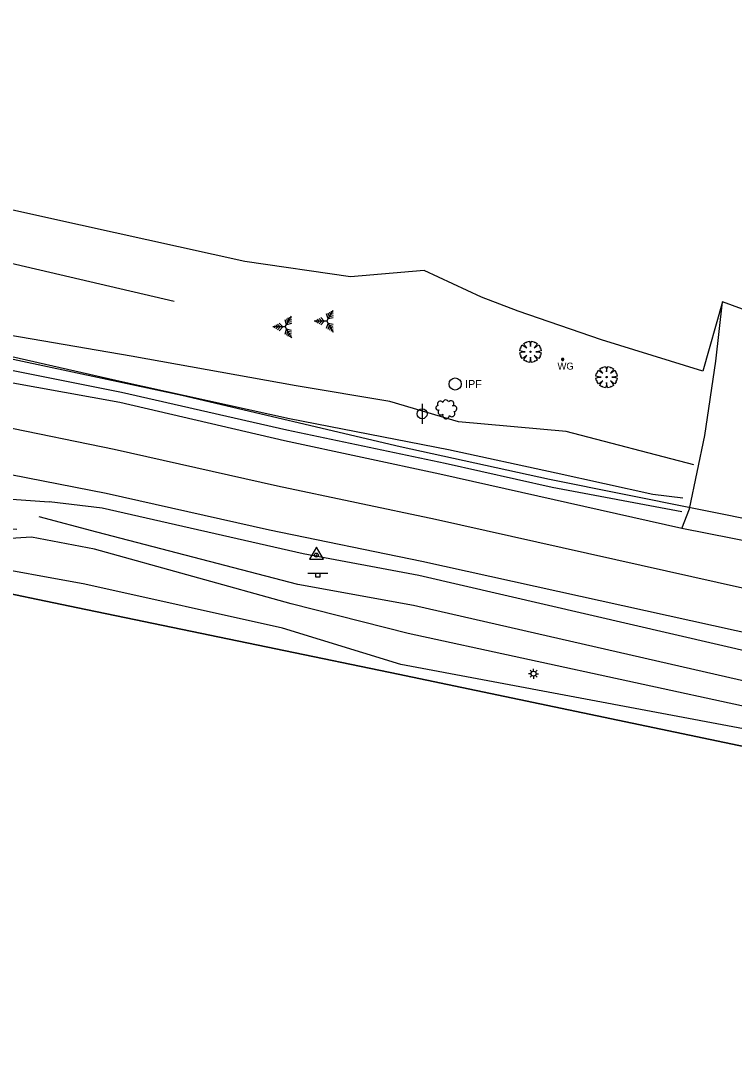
# Model space of a CAD drawing. Extents: x 1158469 to 1165378, y 609843 to 611748.
# Drawn here: x 1164593 to 1164771.4, y 610055.1 to 610312.5 of the extents above; entities that cross this region are included whole.
import ezdxf

# ---------------------------------------------------------------- set-up
doc = ezdxf.new("R2010")
doc.units = 0
for name, color, linetype in [('Exterior Boundary', 7, 'Continuous'), ('S_Control_Temp_Traverse', 7, 'Continuous'), ('S_Fencing_ChainLink', 7, 'Continuous'), ('S_Ground_Elevation', 7, 'Continuous'), ('S_Property_IronPipeFound', 7, 'Continuous'), ('S_Property_Light', 7, 'Continuous'), ('S_Property_Well_GroundElevation', 7, 'Continuous'), ('S_Roadway_Centerline', 7, 'Continuous'), ('S_Roadway_Drive_Gravel', 7, 'Continuous'), ('S_Roadway_Drive_Paved', 7, 'Continuous'), ('S_Roadway_Edge_Pavement', 7, 'Continuous'), ('S_Traffic_Sign_SinglePost', 7, 'Continuous'), ('S_Trees_Bush', 7, 'Continuous'), ('S_Trees_Conifer_NonPay', 7, 'Continuous'), ('S_Trees_Decid_NonPay', 7, 'Continuous'), ('S_Trees_HedgeLine', 7, 'Continuous'), ('S_Utilities_Pole_Power', 7, 'Continuous'), ('S_Utilities_UG_Gas_Line', 7, 'Continuous')]:
    doc.layers.add(name, color=color, linetype=linetype)

msp = doc.modelspace()

# ---------------------------------------------------------------- linework, layer by layer
at = {"layer": 'Exterior Boundary'}
for points in [[(1164903.83, 610193.7), (1164863.2, 610204), (1164861.53, 610205.25), (1164858.1, 610207.6), (1164854.54, 610209.76), (1164852.11, 610211.1), (1164847.14, 610213.54), (1164843.1, 610215.24), (1164841.05, 610216.01), (1164837.94, 610217.07), (1164833.18, 610218.44), (1164768.45, 610242.22), (1164763.58, 610224.84), (1164738.2, 610232.74), (1164717.42, 610239.88), (1164708.24, 610243.35), (1164693.9, 610250.06), (1164675.49, 610248.43), (1164649.1, 610252.28), (1164600.08, 610263.12), (1164566.81, 610270.51)], [(1164407.45, 610200.7), (1164438.65, 610196.65), (1164457.36, 610193.85), (1164478.6, 610190.25), (1164498.72, 610183.81), (1164514.58, 610168.55), (1164581.36, 610170.69), (1164581.72, 610171.1), (1164607.36, 610165.71), (1164656.83, 610155.47), (1164687.39, 610149.15), (1164772.52, 610131.34), (1164815.65, 610122.37), (1164871.7, 610110.37), (1164887.39, 610105.37), (1164928.57, 610096.9)]]:
    msp.add_lwpolyline(points, dxfattribs=at)
at = {"layer": 'S_Control_Temp_Traverse'}
for p, q in [((1164666.85, 610178.9), (1164667.1, 610178.9)), ((1164666.97, 610179.03), (1164666.97, 610178.78))]:
    msp.add_line(p, q, dxfattribs=at)
msp.add_lwpolyline([(1164665.24, 610177.9), (1164668.71, 610177.9), (1164666.97, 610180.9)], close=True, dxfattribs=at)
msp.add_circle((1164666.97, 610178.9), 0.5, dxfattribs=at)
at = {"layer": 'S_Fencing_ChainLink'}
msp.add_lwpolyline([(1164869.51, 610100.35), (1164871.7, 610110.37), (1164815.65, 610122.37), (1164772.52, 610131.34), (1164687.39, 610149.15), (1164656.83, 610155.47), (1164607.36, 610165.71), (1164581.72, 610171.1), (1164574.63, 610139.83), (1164560.56, 610143.01)], dxfattribs=at)
at = {"layer": 'S_Ground_Elevation'}
for points in [[(1164763.58, 610224.84), (1164738.2, 610232.74), (1164717.42, 610239.88), (1164708.24, 610243.35), (1164693.9, 610250.06), (1164675.49, 610248.43), (1164649.1, 610252.28), (1164600.08, 610263.12), (1164566.81, 610270.51), (1164538.66, 610273.93), (1164498.09, 610279.94), (1164480.73, 610283.61), (1164457.41, 610282.8), (1164453.66, 610297.23), (1164453.93, 610312.49)], [(1164761.29, 610201.44), (1164729.39, 610209.78), (1164702.48, 610212.22), (1164685.33, 610217.31), (1164661.9, 610221.24), (1164620.7, 610228.6), (1164590.08, 610233.86), (1164556.37, 610241.22), (1164527.86, 610249.08), (1164496.26, 610253.68), (1164468.26, 610259.85), (1164455.55, 610263.46)], [(1164758.29, 610189.71), (1164725.91, 610195.8), (1164699.15, 610201.83), (1164659.56, 610210.14), (1164618.3, 610219.54), (1164588.26, 610225.54), (1164554.8, 610231.9), (1164525.78, 610237.71), (1164494.09, 610244.67), (1164467.1, 610249.14), (1164452.39, 610252.67), (1164442.78, 610255.45), (1164439.6, 610257.87), (1164438.33, 610260.82)], [(1164758.56, 610193.13), (1164751.06, 610194.06), (1164726.93, 610199.41), (1164699.99, 610205.18), (1164660.26, 610212.97), (1164618.7, 610222.1), (1164589.01, 610228.9), (1164555.36, 610235.61), (1164526.59, 610241.94), (1164495.09, 610248.39), (1164467.66, 610253.8), (1164454.39, 610257.4), (1164441.36, 610259.91)], [(1164937.87, 610100.73), (1164888.97, 610111.32), (1164813.69, 610124.81), (1164773.68, 610135.52), (1164688.09, 610151.59), (1164658.53, 610160.64), (1164609.13, 610171.64), (1164581.57, 610176.61), (1164575.27, 610182.72), (1164576.93, 610186.53), (1164581.1, 610189.86), (1164590.89, 610192.87), (1164600.18, 610192.25)], [(1164949.24, 610096.19), (1164972.18, 610091.41), (1165006.8, 610084.96), (1165049.11, 610075.28), (1165077.78, 610072.21), (1165082.39, 610077.32), (1165083.55, 610085.15), (1165057.81, 610094.68), (1165021.71, 610103.76), (1164992.93, 610110.39), (1164953.46, 610118.26), (1164916.46, 610126.06), (1164891.26, 610129.22), (1164870.42, 610136.28), (1164819.53, 610147.22), (1164777.52, 610154.18), (1164692.53, 610173.85), (1164663.65, 610179.23), (1164613.39, 610190.6), (1164600.18, 610192.25)], [(1164949.51, 610110.94), (1164891.13, 610123.39), (1164817.42, 610139.44), (1164776.14, 610146.9), (1164691.23, 610166.29), (1164662.34, 610171.55), (1164612.06, 610184.67), (1164597.68, 610188.51)], [(1164946.72, 610105.38), (1164890.19, 610118.57), (1164815.41, 610133.93), (1164775.15, 610140.78), (1164689.92, 610159.35), (1164660.69, 610166.76), (1164611.52, 610180.36), (1164595.78, 610183.41), (1164582.5, 610182.59), (1164578.91, 610185.44), (1164583.71, 610185.64), (1164592.14, 610185.36)]]:
    msp.add_lwpolyline(points, dxfattribs=at)
at = {"layer": 'S_Property_IronPipeFound'}
msp.add_circle((1164701.64, 610221.67), 1.5, dxfattribs=at)
at = {"layer": 'S_Property_Light'}
for p, q in [((1164720.81, 610149.71), (1164720.37, 610150.15)), ((1164721.25, 610149.9), (1164721.25, 610150.52)), ((1164721.69, 610149.71), (1164722.13, 610150.15)), ((1164720.62, 610149.27), (1164720, 610149.27)), ((1164720.81, 610148.83), (1164720.37, 610148.39)), ((1164721.25, 610148.65), (1164721.25, 610148.02)), ((1164721.69, 610148.83), (1164722.13, 610148.39)), ((1164721.87, 610149.27), (1164722.5, 610149.27))]:
    msp.add_line(p, q, dxfattribs=at)
msp.add_circle((1164721.25, 610149.27), 0.625, dxfattribs=at)
at = {"layer": 'S_Property_Well_GroundElevation'}
for p, q in [((1164728.9, 610227.78), (1164728.11, 610227.78)), ((1164728.77, 610227.51), (1164728.24, 610228.04)), ((1164728.77, 610228.04), (1164728.24, 610227.51)), ((1164728.5, 610228.17), (1164728.5, 610227.38))]:
    msp.add_line(p, q, dxfattribs=at)
at = {"layer": 'S_Roadway_Centerline'}
msp.add_lwpolyline([(1165322.92, 610055.12), (1165282.59, 610063.58), (1165267.59, 610066.74), (1165234.97, 610073.48), (1165207.29, 610078.95), (1165170.95, 610086.9), (1165118.3, 610098.03), (1165065.91, 610108.93), (1165025.19, 610117.35), (1164995.59, 610123.89), (1164956.04, 610131.83), (1164919.32, 610140.12), (1164874.11, 610149.34), (1164822.77, 610160.96), (1164779.77, 610169.22), (1164696.7, 610187.78), (1164657.25, 610196.14), (1164616.44, 610205.3), (1164588.01, 610211.13), (1164540.84, 610220.89), (1164515.97, 610226.08), (1164470.96, 610235.38), (1164428.02, 610243.9), (1164400.81, 610249.16)], dxfattribs=at)
at = {"layer": 'S_Roadway_Drive_Gravel'}
msp.add_lwpolyline([(1164758.26, 610185.55), (1164760.21, 610190.5), (1164764.08, 610208.8), (1164766.82, 610227.35), (1164768.45, 610242.22)], dxfattribs=at)
at = {"layer": 'S_Roadway_Drive_Paved'}
msp.add_lwpolyline([(1165087.67, 610085.66), (1165088.73, 610081.37), (1165088.66, 610075.08), (1165086.95, 610069.17), (1165080.91, 610064.92), (1165078.44, 610064.65), (1165053.51, 610069.94), (1165023.36, 610076.76), (1164985.09, 610084.83), (1164949.13, 610091.57), (1164928.57, 610096.9), (1164887.39, 610105.37), (1164871.7, 610110.37), (1164815.65, 610122.37), (1164772.52, 610131.34), (1164687.39, 610149.15), (1164656.83, 610155.47), (1164607.36, 610165.71), (1164581.72, 610171.1)], dxfattribs=at)
at = {"layer": 'S_Roadway_Edge_Pavement'}
for points in [[(1164919.8, 610151.45), (1164879.24, 610159.72), (1164823.73, 610172.33), (1164795.86, 610178.14), (1164758.26, 610185.55), (1164697.81, 610199.14), (1164659.01, 610207.49), (1164617.87, 610217.04), (1164590.19, 610222.02), (1164544.28, 610231.49), (1164517.23, 610237.09), (1164473.1, 610245.96), (1164441.43, 610253.11), (1164405.39, 610259.57)], [(1164917.37, 610129.44), (1164871.2, 610138.85), (1164820.1, 610150.09), (1164777.51, 610158.77), (1164693.3, 610177.3), (1164655.28, 610185.18), (1164614.45, 610194.3), (1164586.72, 610199.72), (1164516.67, 610214.63), (1164468.95, 610224.66), (1164425.43, 610233.22)]]:
    msp.add_lwpolyline(points, dxfattribs=at)
at = {"layer": 'S_Traffic_Sign_SinglePost'}
msp.add_line((1164664.79, 610174.42), (1164669.79, 610174.42), dxfattribs=at)
msp.add_lwpolyline([(1164666.79, 610174.42), (1164667.79, 610174.42), (1164667.79, 610173.42), (1164666.79, 610173.42)], close=True, dxfattribs=at)
at = {"layer": 'S_Trees_Bush'}
for centre, radius, start, end in [((1164697.93, 610216.68), 0.717, 33.6405, 213.5909), ((1164699.29, 610216.91), 0.776, 19.7277, 168.0032), ((1164700.61, 610216.77), 0.715, 304.7168, 145.2832), ((1164697.39, 610215.71), 0.576, 95.1875, 295.4615), ((1164698.08, 610214.64), 0.706, 129.1555, 309.4105), ((1164699.36, 610213.85), 0.862, 163.7427, 356.276), ((1164700.81, 610214.24), 0.742, 216.9809, 47.4965), ((1164701.33, 610215.52), 0.733, 268.122, 116.0172)]:
    msp.add_arc(centre, radius, start, end, dxfattribs=at)
at = {"layer": 'S_Trees_Conifer_NonPay'}
for p, q in [((1164669.57, 610237.38), (1164671.14, 610240.1)), ((1164670.51, 610239.01), (1164670.33, 610239.64)), ((1164670.83, 610239.55), (1164670.74, 610239.87)), ((1164671.14, 610239.64), (1164670.83, 610239.55)), ((1164659.49, 610236.46), (1164659.14, 610237.71)), ((1164659.18, 610235.92), (1164660.75, 610238.64)), ((1164659.81, 610237), (1164659.54, 610237.94)), ((1164660.75, 610237.24), (1164659.81, 610237)), ((1164660.12, 610237.55), (1164659.94, 610238.17)), ((1164660.75, 610237.71), (1164660.12, 610237.55)), ((1164660.44, 610238.09), (1164660.35, 610238.4)), ((1164660.75, 610238.17), (1164660.44, 610238.09)), ((1164669.57, 610237.38), (1164666.42, 610237.38)), ((1164667.05, 610237.38), (1164666.83, 610237.61)), ((1164666.83, 610237.15), (1164667.05, 610237.38)), ((1164667.68, 610237.38), (1164667.23, 610237.85)), ((1164667.23, 610236.91), (1164667.68, 610237.38)), ((1164668.31, 610237.38), (1164667.64, 610238.08)), ((1164667.64, 610236.68), (1164668.31, 610237.38)), ((1164668.94, 610237.38), (1164668.04, 610238.31)), ((1164668.04, 610236.45), (1164668.94, 610237.38)), ((1164669.88, 610237.92), (1164669.52, 610239.17)), ((1164669.57, 610237.38), (1164671.14, 610234.66)), ((1164671.14, 610238.23), (1164669.88, 610237.92)), ((1164670.2, 610238.47), (1164669.93, 610239.4)), ((1164671.14, 610238.7), (1164670.2, 610238.47)), ((1164671.14, 610239.17), (1164670.51, 610239.01)), ((1164659.18, 610235.92), (1164656.04, 610235.92)), ((1164656.67, 610235.92), (1164656.44, 610236.15)), ((1164656.44, 610235.68), (1164656.67, 610235.92)), ((1164657.29, 610235.92), (1164656.84, 610236.38)), ((1164656.84, 610235.45), (1164657.29, 610235.92)), ((1164657.92, 610235.92), (1164657.25, 610236.62)), ((1164657.25, 610235.22), (1164657.92, 610235.92)), ((1164658.55, 610235.92), (1164657.65, 610236.85)), ((1164657.65, 610234.98), (1164658.55, 610235.92)), ((1164659.14, 610234.13), (1164659.49, 610235.37)), ((1164659.18, 610235.92), (1164660.75, 610233.19)), ((1164660.75, 610236.77), (1164659.49, 610236.46)), ((1164660.75, 610235.06), (1164659.49, 610235.37)), ((1164659.54, 610233.9), (1164659.81, 610234.83)), ((1164660.75, 610234.6), (1164659.81, 610234.83)), ((1164669.52, 610235.59), (1164669.88, 610236.83)), ((1164671.14, 610236.52), (1164669.88, 610236.83)), ((1164669.93, 610235.36), (1164670.2, 610236.29)), ((1164671.14, 610236.06), (1164670.2, 610236.29)), ((1164670.33, 610235.12), (1164670.51, 610235.75)), ((1164671.14, 610235.59), (1164670.51, 610235.75)), ((1164670.74, 610234.89), (1164670.83, 610235.2)), ((1164671.14, 610235.12), (1164670.83, 610235.2)), ((1164659.94, 610233.66), (1164660.12, 610234.28)), ((1164660.75, 610234.13), (1164660.12, 610234.28)), ((1164660.35, 610233.43), (1164660.44, 610233.74)), ((1164660.75, 610233.66), (1164660.44, 610233.74))]:
    msp.add_line(p, q, dxfattribs=at)
at = {"layer": 'S_Trees_Decid_NonPay'}
for points in [[(1164719.14, 610229.73), (1164718.45, 610229.78), (1164717.82, 610230), (1164717.97, 610230.69), (1164718.13, 610230.69), (1164718.08, 610230.9), (1164718.4, 610231.43), (1164718.93, 610231.16), (1164719.52, 610230.69), (1164719.04, 610231.27), (1164718.77, 610231.8), (1164719.3, 610232.12), (1164719.52, 610232.07), (1164719.52, 610232.23), (1164720.21, 610232.39), (1164720.42, 610231.75), (1164720.47, 610231.06), (1164720.53, 610231.75), (1164720.74, 610232.39), (1164721.43, 610232.23), (1164721.43, 610232.07), (1164721.64, 610232.12), (1164722.17, 610231.8), (1164721.91, 610231.27), (1164721.43, 610230.69), (1164722.01, 610231.16), (1164722.55, 610231.43), (1164722.86, 610230.9), (1164722.81, 610230.69), (1164722.97, 610230.69), (1164723.13, 610230), (1164722.49, 610229.78), (1164721.8, 610229.73), (1164722.49, 610229.68), (1164723.13, 610229.46), (1164722.97, 610228.77), (1164722.81, 610228.77), (1164722.86, 610228.56), (1164722.55, 610228.03), (1164722.01, 610228.29), (1164721.43, 610228.77), (1164721.91, 610228.19), (1164722.17, 610227.66), (1164721.64, 610227.34), (1164721.43, 610227.39), (1164721.43, 610227.23), (1164720.74, 610227.07), (1164720.53, 610227.71), (1164720.47, 610228.4), (1164720.42, 610227.71), (1164720.21, 610227.07), (1164719.52, 610227.23), (1164719.52, 610227.39), (1164719.3, 610227.34), (1164718.77, 610227.66), (1164719.04, 610228.19), (1164719.52, 610228.77), (1164718.93, 610228.29), (1164718.4, 610228.03), (1164718.08, 610228.56), (1164718.13, 610228.77), (1164717.97, 610228.77), (1164717.82, 610229.46), (1164718.45, 610229.68), (1164719.14, 610229.73)], [(1164738.17, 610223.39), (1164737.48, 610223.44), (1164736.84, 610223.66), (1164737, 610224.35), (1164737.16, 610224.35), (1164737.11, 610224.56), (1164737.43, 610225.09), (1164737.96, 610224.82), (1164738.54, 610224.35), (1164738.06, 610224.93), (1164737.8, 610225.46), (1164738.33, 610225.78), (1164738.54, 610225.73), (1164738.54, 610225.89), (1164739.23, 610226.05), (1164739.45, 610225.41), (1164739.5, 610224.72), (1164739.55, 610225.41), (1164739.76, 610226.05), (1164740.46, 610225.89), (1164740.46, 610225.73), (1164740.67, 610225.78), (1164741.2, 610225.46), (1164740.93, 610224.93), (1164740.46, 610224.35), (1164741.04, 610224.82), (1164741.57, 610225.09), (1164741.89, 610224.56), (1164741.84, 610224.35), (1164742, 610224.35), (1164742.16, 610223.66), (1164741.52, 610223.44), (1164740.83, 610223.39), (1164741.52, 610223.34), (1164742.16, 610223.12), (1164742, 610222.43), (1164741.84, 610222.43), (1164741.89, 610222.22), (1164741.57, 610221.69), (1164741.04, 610221.95), (1164740.46, 610222.43), (1164740.93, 610221.85), (1164741.2, 610221.32), (1164740.67, 610221), (1164740.46, 610221.05), (1164740.46, 610220.89), (1164739.76, 610220.73), (1164739.55, 610221.37), (1164739.5, 610222.06), (1164739.45, 610221.37), (1164739.23, 610220.73), (1164738.54, 610220.89), (1164738.54, 610221.05), (1164738.33, 610221), (1164737.8, 610221.32), (1164738.06, 610221.85), (1164738.54, 610222.43), (1164737.96, 610221.95), (1164737.43, 610221.69), (1164737.11, 610222.22), (1164737.16, 610222.43), (1164737, 610222.43), (1164736.84, 610223.12), (1164737.48, 610223.34), (1164738.17, 610223.39)]]:
    msp.add_lwpolyline(points, dxfattribs=at)
for centre in [(1164720.47, 610229.73), (1164739.5, 610223.39)]:
    msp.add_circle(centre, 0.167, dxfattribs=at)
at = {"layer": 'S_Trees_HedgeLine'}
msp.add_lwpolyline([(1164631.45, 610242.28), (1164542.05, 610263.12), (1164476.17, 610269.26)], dxfattribs=at)
at = {"layer": 'S_Utilities_Pole_Power'}
msp.add_line((1164693.39, 610216.73), (1164693.39, 610211.73), dxfattribs=at)
msp.add_circle((1164693.39, 610214.23), 1.25, dxfattribs=at)
at = {"layer": 'S_Utilities_UG_Gas_Line'}
msp.add_lwpolyline([(1164523.25, 610240.99), (1164578.61, 610230.52), (1164633.3, 610218.87), (1164687.87, 610206.09), (1164725.23, 610197.92), (1164780.39, 610186.82), (1164833.41, 610174.66), (1164886.88, 610163.44), (1164937.79, 610151.89), (1164988.92, 610140.46), (1164992, 610140.14)], dxfattribs=at)

# ---------------------------------------------------------------- texts
at = {"layer": 'S_Property_IronPipeFound'}
msp.add_text('IPF', height=2, dxfattribs=at).set_placement((1164704.14, 610220.67))
at = {"layer": 'S_Property_Well_GroundElevation'}
msp.add_text('WG', height=1.75, rotation=360, dxfattribs=at).set_placement((1164727.23, 610225.26))

doc.saveas('drawing.dxf')
